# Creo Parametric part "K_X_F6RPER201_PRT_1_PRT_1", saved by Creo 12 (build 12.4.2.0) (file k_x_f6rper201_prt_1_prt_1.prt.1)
Units: Custom; MM, KILOGRAM, SECS

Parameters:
  PTC_WM_ITERATION = "0"
  PTC_WM_VERSION = "-.0"
  PTC_WM_LIFECYCLE_STATE = "In Work"
  PTC_WM_LIFECYCLE = "MO_CADDocument"
  PTC_WM_CREATED_BY = "Maximilian Roepper (Z0017RMS: MO)"
  PTC_WM_CREATED_ON = "18-Sep-26 11:36:42 AM"
  PTC_WM_MODIFIED_BY = "Maximilian Roepper (Z0017RMS: MO)"
  PTC_WM_MODIFIED_ON = "18-Sep-26 11:36:46 AM"
  PDMLINKNUMBER = "PDM000071455207"
  PTC_WM_NAME = "k_x_f6rper201_prt_1_prt_1.prt"
  PTC_WM_NUMBER = "PDM000071455207"

Other parameters: WEIGHT, WEIGHT_FACTOR, WEIGHT_ADD, _MASS_TEMP, _DIFF_TEMP, MC_ERRORS, SUPPLIER

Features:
  1. coordinate system
  2. datum plane "PRT_YZ"
  3. datum plane "PRT_XY"
  4. datum plane "PRT_XZ"
  5. coordinate system
  6. datum axis
  7. datum axis
  8. datum axis
  9. coordinate system
  10. imported feature
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
Other named items: PRT, SIEMENS_MO, DRW_VIEW_ORG, PRT_X, PRT_Y, PRT_Z, CS0, ROUGH_GROB

Layers: 00_STD_CSYS-KSYS, 01_STD_PLANES-EBENEN, 02_STD_AXES-ACHSEN, 03_STD_CSYS-KSYS, 24_IMPORT_FEAT-IMPORT_KE

Surfaces: 6 plane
